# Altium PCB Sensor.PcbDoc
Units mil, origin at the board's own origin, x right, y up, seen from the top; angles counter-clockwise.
Board outline 4560.03 x 3240.01 mil, 2 copper layers (Top Layer, Bottom Layer); 112 components, 74 nets, 343 pads, 74 vias.
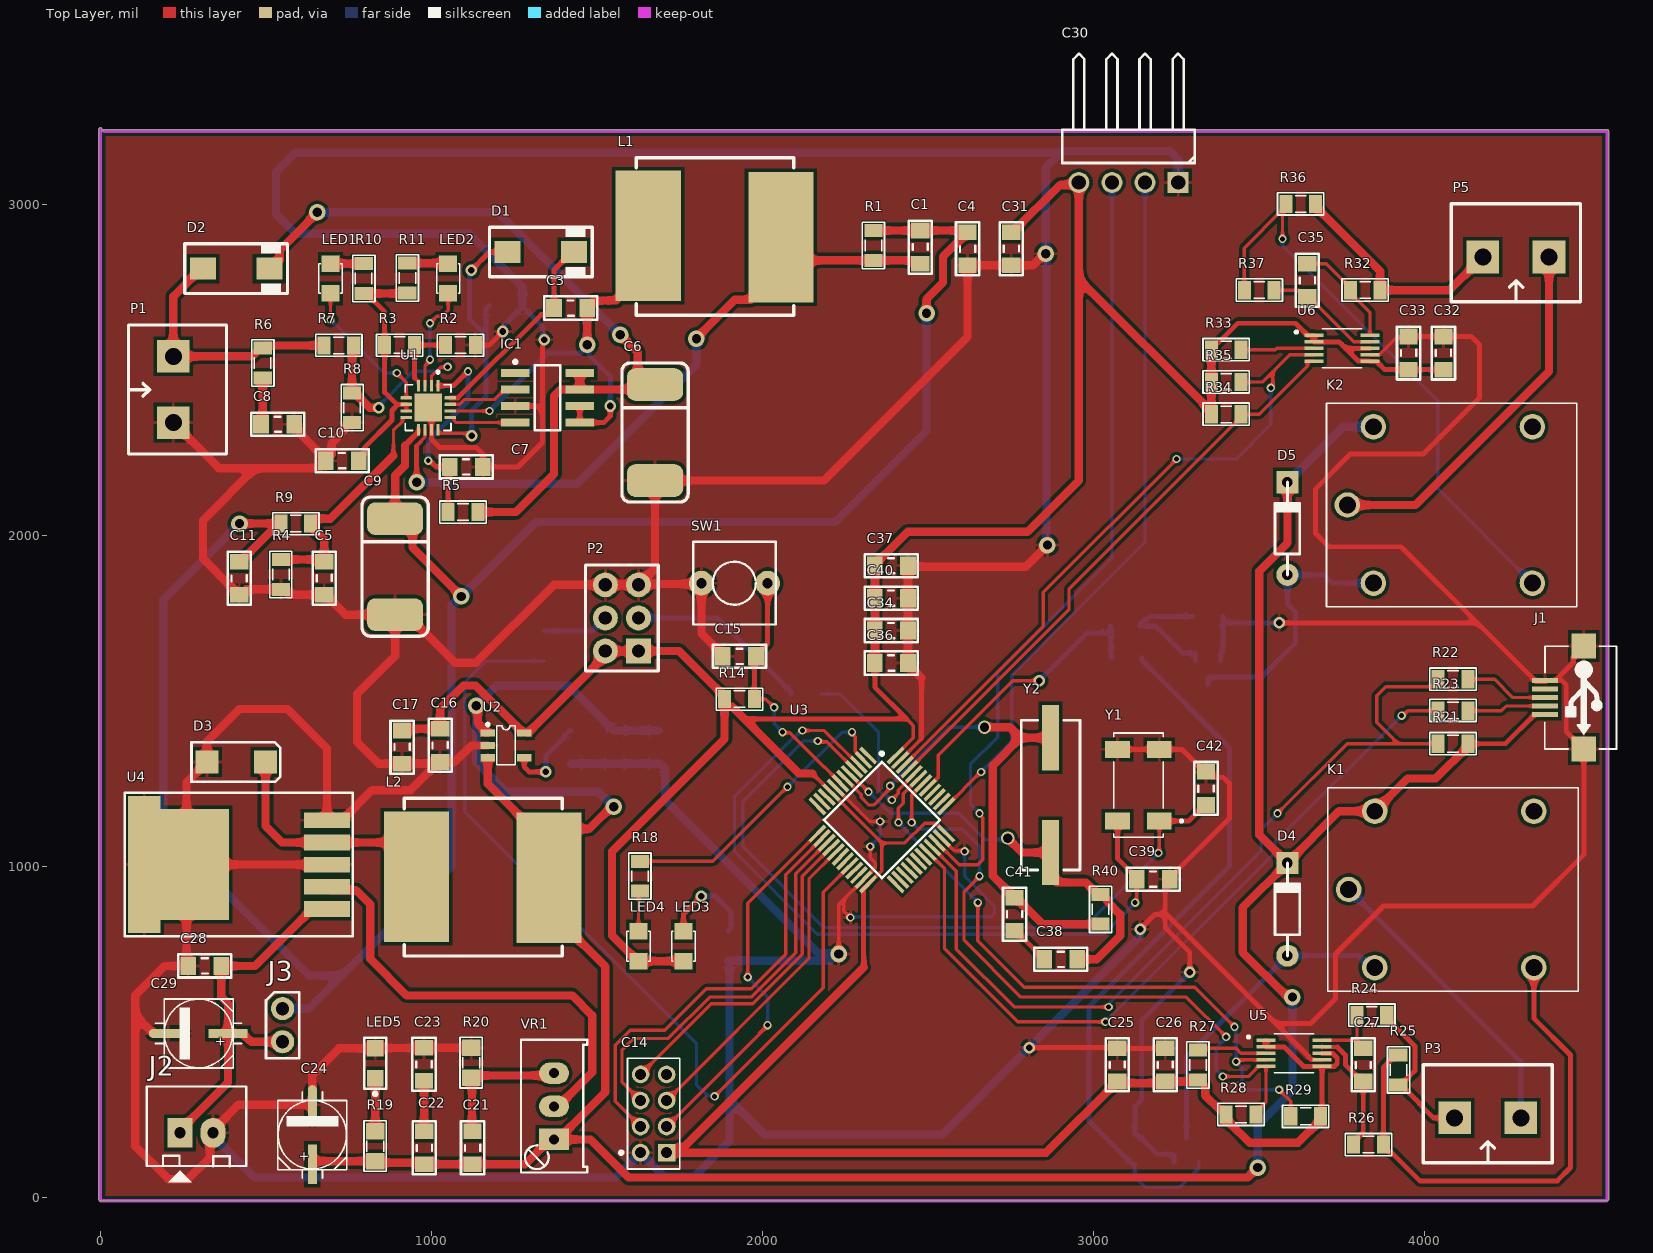
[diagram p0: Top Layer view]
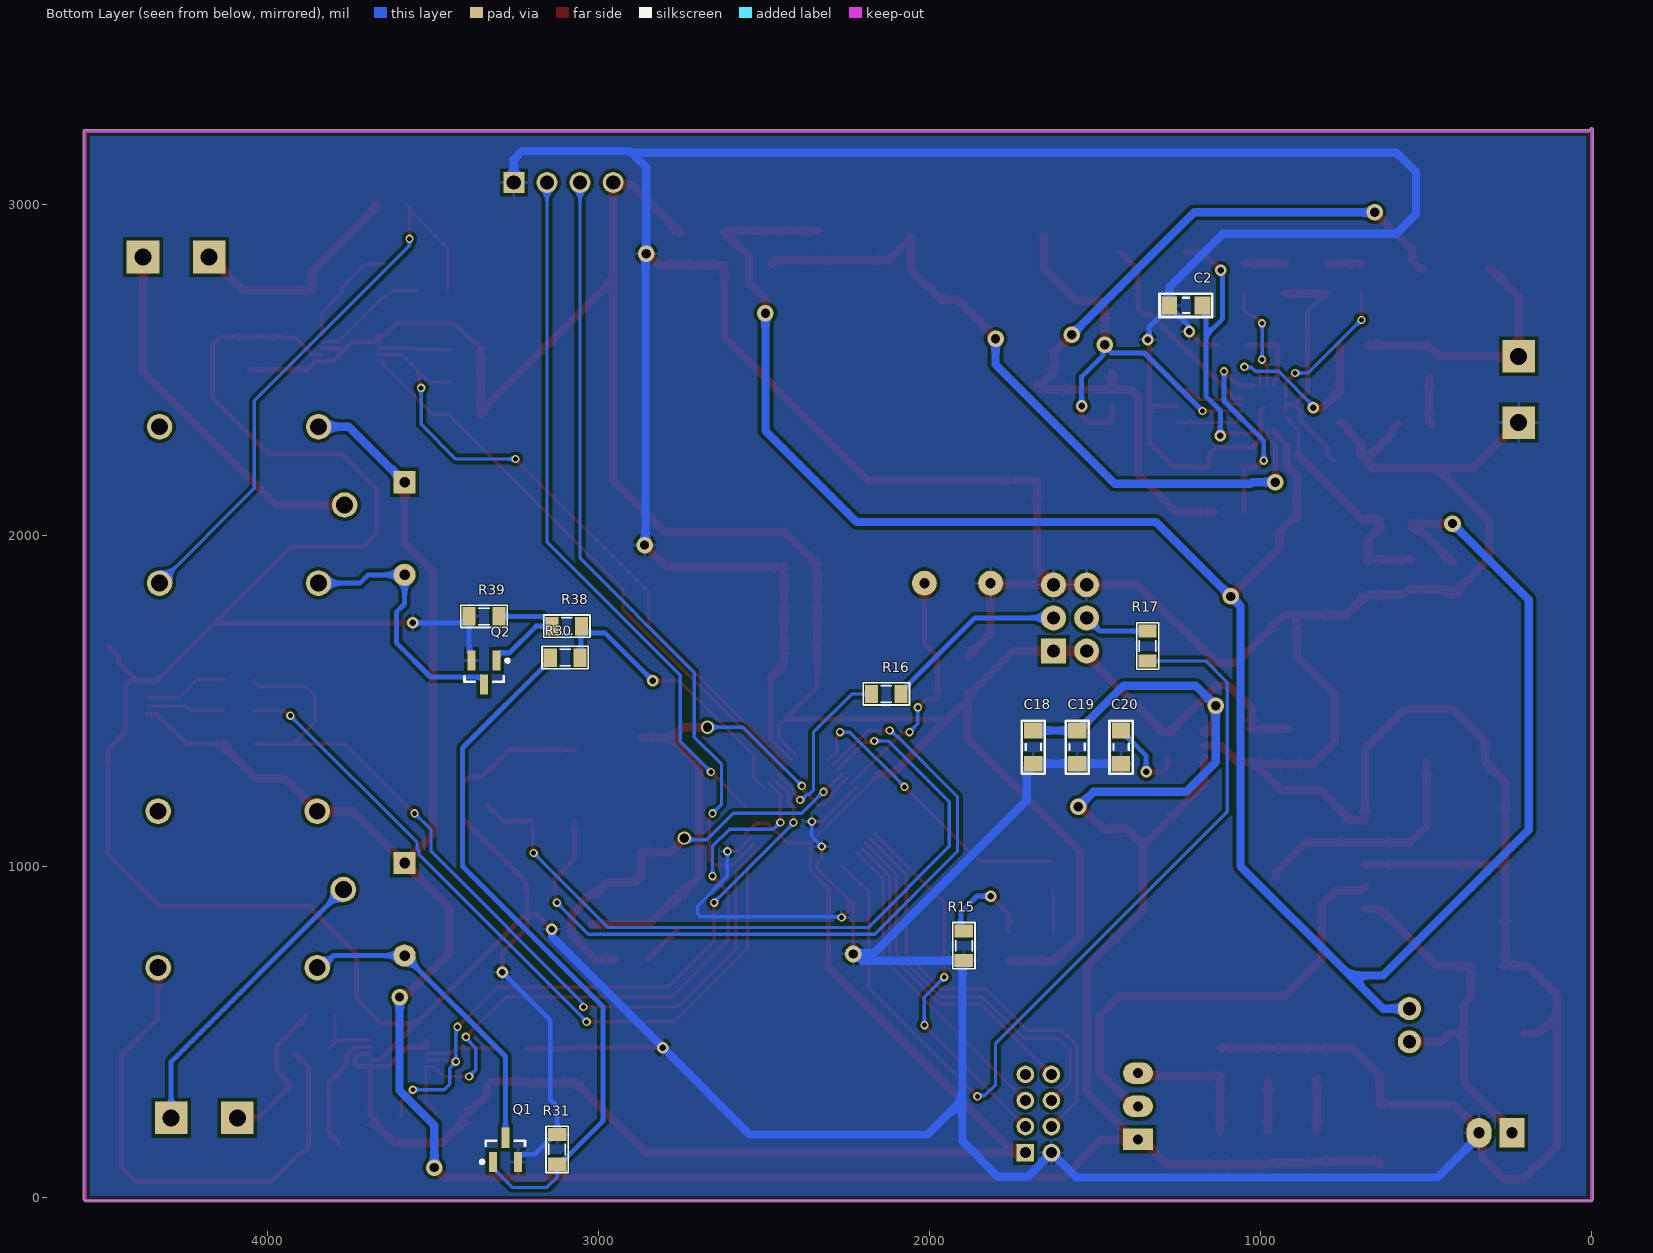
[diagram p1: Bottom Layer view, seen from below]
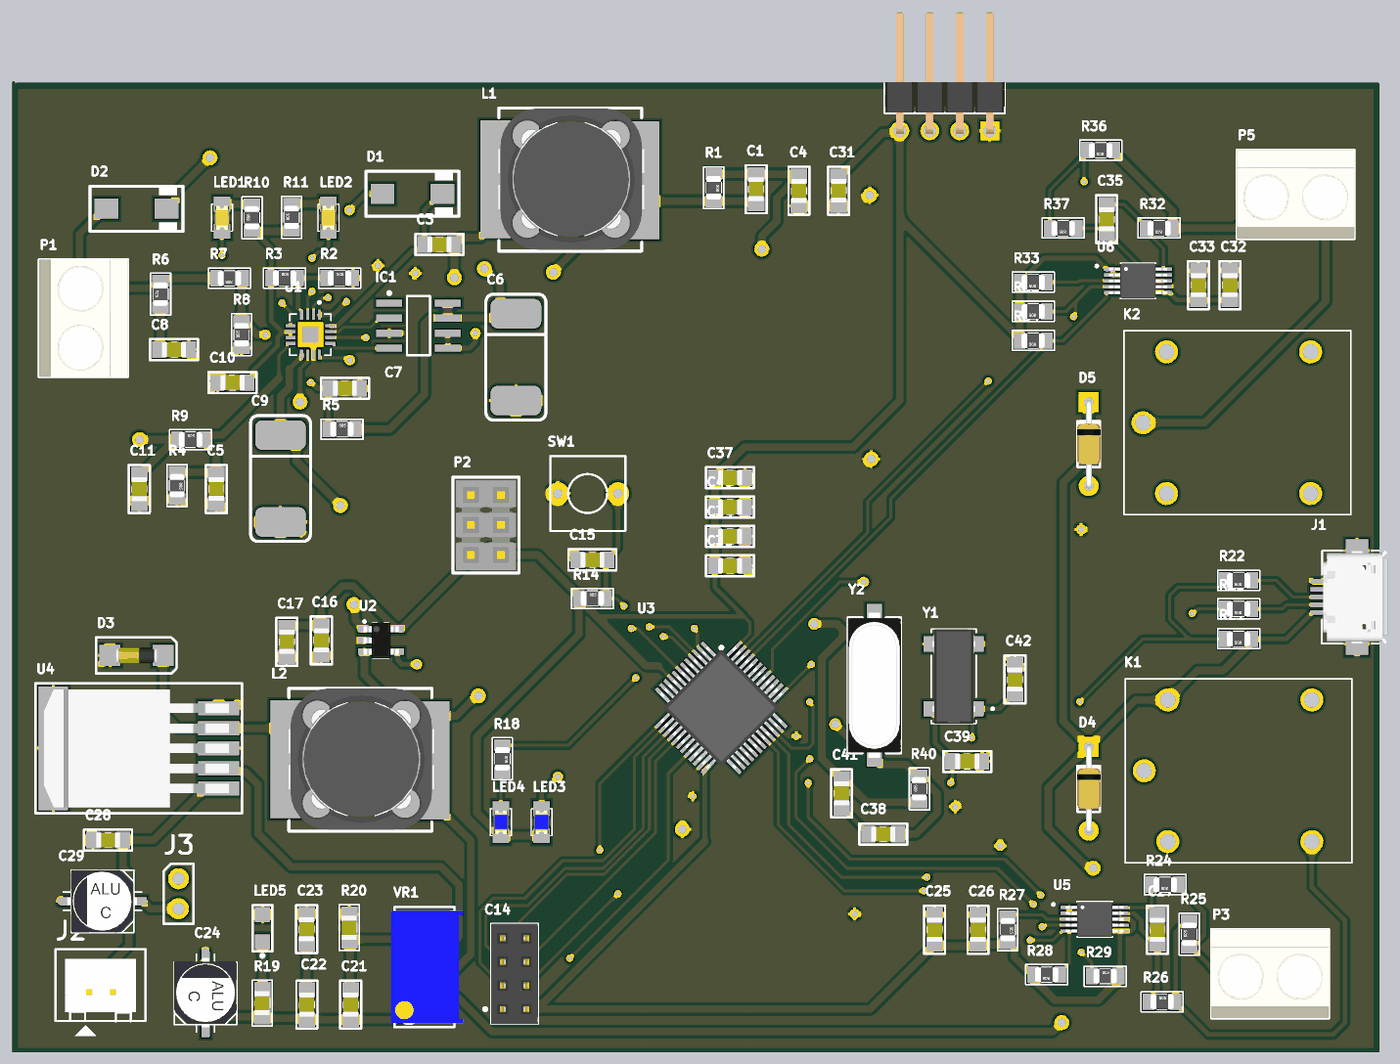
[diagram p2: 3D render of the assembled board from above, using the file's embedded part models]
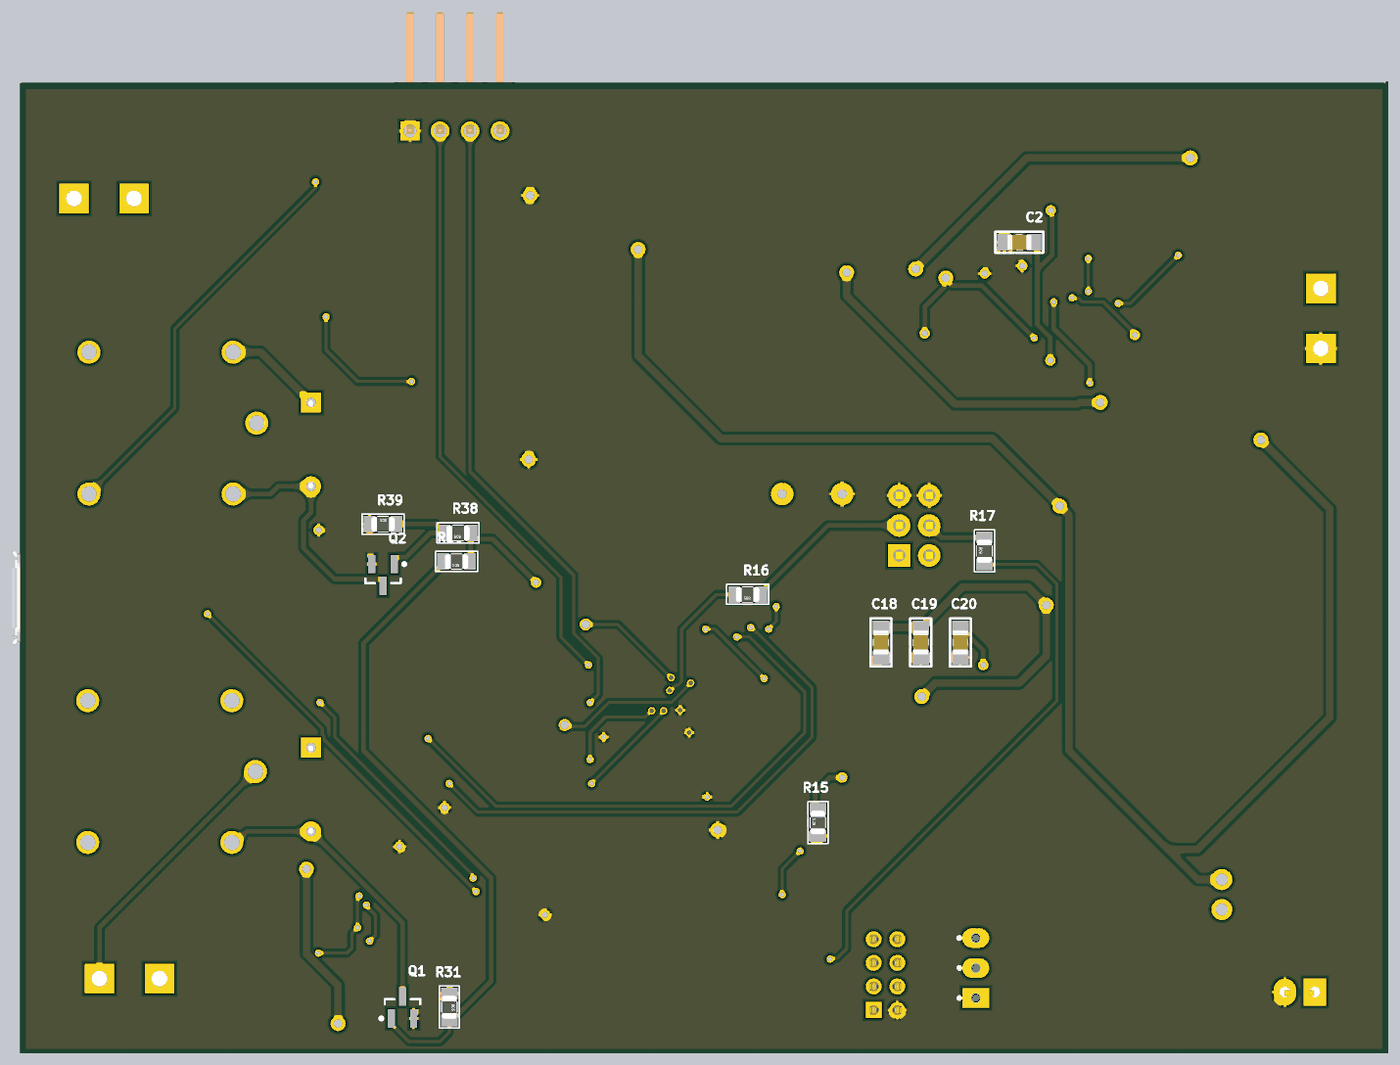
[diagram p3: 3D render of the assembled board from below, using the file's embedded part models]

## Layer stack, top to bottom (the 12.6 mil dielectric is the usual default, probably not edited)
Top Solder: solder mask 0.4, Solder Resist, Dk 3.5
Top Layer: signal copper 1.4
Dielectric 1: dielectric 12.6, FR-4, Dk 4.8
Bottom Layer: signal copper 1.4
Bottom Solder: solder mask 0.4, Solder Resist, Dk 3.5

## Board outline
0,-10.02 cw(c0,-5) -5.02,-5 -5.02,3225 cw(c0,3225) 5.02,3225 5.02,3220.55 cw(c10,3220) 10,3225.02 4550,3225.02 cw(c4550,3220) 4555.02,3220 4555.02,-5 cw(c4550,-5) 4550,-10.02

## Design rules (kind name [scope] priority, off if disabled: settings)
Clearance [All] p1: gap=10 ignorepadtopadclearanceinfootprint=FALSE
PolygonConnect [All] p1: connectstyle=Relief reliefconductorwidth=10 reliefentries=4 polygonreliefangle="90 Angle" airgapwidth=10
RoutingVias [All] p1: holewidth=20 width=35 viastyle="Through Hole" minholewidth=15 minwidth=25 maxholewidth=28 maxwidth=50
SilkToSilkClearance [IsText] p1: silktosilkclearance=10
SolderMaskExpansion [All] p1: expansion=4 istentingtop=FALSE
Width [All] p1: maxlimit=25 minlimit=10 preferedwidth=15
29 further rules are at their usual default settings.

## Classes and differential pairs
component class U_Sensor: C14 C15 C16 C17 C18 C19 C20 C21 C22 C23 C24 C25 C26 C27 C28 C29 C30 C31 C32 C33 C34 C35 C36 C37 C38 C39 C40 C41 C42 D3 D4 D5 J1 K1 K2 L2 LED3 LED4 LED5 P2 P3 P5 Q1 Q2 R14 R15 R16 R17 R18 R19 R20 R21 R22 R23 R24 R25 R26 R27 R28 R29 R30 R31 R32 R33 R34 R35 R36 R37 R38 R39 R40 SW1 U2 U3 U4 U5 U6 VR1 Y1 Y2
component class U_MPPT: C1 C2 C3 C4 C5 C6 C7 C8 C9 C10 C11 D1 D2 IC1 J2 J3 L1 LED1 LED2 P1 R1 R2 R3 R4 R5 R6 R7 R8 R9 R10 R11 U1

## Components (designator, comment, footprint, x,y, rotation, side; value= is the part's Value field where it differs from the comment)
C1 "10uF" CAP_0805 2475,2870 r90 top value=33p
C2 "2.2uF" CAP_0805 1225,2695 r180 bottom value=33p
C3 "2.2uF" CAP_0805 1420,2687 r0 top value=33p
C4 "10uF" CAP_0805 2620,2865 r270 top value=33p
C5 "100uF" CAP_0805 675,1870 r90 top value=33p
C6 "220uF/25V" CAP_7343 1675,2305 r270 top
C7 "100nF" CAP_0805 1105,2205 r180 top value=33p
C8 "2.2uF" CAP_0805 535,2336 r0 top value=33p
C9 "100uF/16V" CAP_7343 890,1900 r270 top
C10 "0.1nF" CAP_0805 730,2224 r180 top value=33p
C11 "22uF" CAP_0805 420,1870 r270 top value=33p
C14 "JP4x2-2.0" J4-C2T 1670.63,253.11 r90 top
C15 "105" CAP_0805 1930,1635 r0 top value=33p
C16 "106" CAP_0805 1025,1365 r90 top value=33p
C17 "104" CAP_0805 910,1360 r90 top value=33p
C18 "105" CAP_0805 1687,1360 r90 bottom value=33p
C19 "104" CAP_0805 1554.5,1360 r90 bottom value=33p
C20 "223" CAP_0805 1422,1360 r90 bottom value=33p
C21 "22pF" CAP_0805 1125,150 r270 top
C22 "100nF/50V" CAP_0805 979.22,150 r270 top
C23 "100nF/50V" CAP_0805 978.22,402 r270 top
C24 "Cap Pol SMD" CAP-ALU-SMD-C 640,190 r90 top value=100uF/63V
C25 "0.1uF" CAP_0805 3070,400 r90 top value=33p
C26 "0.1uF" CAP_0805 3215,400 r90 top value=33p
C27 "0.1uF" CAP_0805 3815,400 r270 top value=33p
C28 "1uF/50V" CAP_0805 315,700 r0 top
C29 "Cap Pol SMD" CAP-ALU-SMD-C 295,495 r180 top value=100uF/50V
C30 "JP4" JP4-D1C 2905,3165 r180 top
C31 "104" CAP_0805 2750,2865 r90 top value=33p
C32 "0.1uF" CAP_0805 4055,2550 r90 top value=33p
C33 "0.1uF" CAP_0805 3950,2550 r90 top value=33p
C34 "104" CAP_0805 2388.94,1710.81 r180 top value=33p
C35 "0.1uF" CAP_0805 3646,2770 r270 top value=33p
C36 "104" CAP_0805 2388.94,1612.94 r180 top value=33p
C37 "104" CAP_0805 2388.94,1906.56 r180 top value=33p
C38 "20p" CAP_0805 2900,720 r0 top value=33p
C39 "20p" CAP_0805 3180,960 r180 top value=33p
C40 "104" CAP_0805 2388.94,1808.68 r180 top value=33p
C41 "20p" CAP_0805 2760,855 r90 top value=33p
C42 "20p" CAP_0805 3340,1235 r270 top value=33p
D1 "1N5822" SMA 1330,2855 r0 top value="Diode c?m 1N5408"
D2 "1N5822" SMA 409.84,2805 r0 top value="Diode c?m 1N5408"
D3 "Diode Zener" DIODE_ZENER_SMD 410,1315 r0 top
D4 "Diode 1N4148" DO-35 3585,870 r90 top
D5 "Diode 1N4148" DO-35 3585,2020 r90 top
IC1 "AO4914" Soic-8 1350,2405 r0 top
J1 "USB-5" USB-M1 4363.16,1509.49 r270 top
J2 "JP2" CON2 240,195 r0 top
J3 "JP2" JP2-CLOSED 550,570 r0 top
K1 "SRD-03VDC-SL-C" RELAY_SRD-03VDC-SL-C 4085,930 r0 top
K2 "SRD-03VDC-SL-C" RELAY_SRD-03VDC-SL-C 4080.91,2091.22 r0 top
L1 "15uH" Inductor_SMD 2094.37,2663.78 r90 top value="150 mH"
L2 "33uH" Inductor_SMD 1394.37,728.78 r90 top value="150 mH"
LED1 "LED" LED-0805-Yellow 695,2820 r270 top value="LED 3 ly Single Colour"
LED2 "LED" LED-0805-Yellow 1050,2820 r270 top value="LED 3 ly Single Colour"
LED3 "LED" LED-0805-Blue 1760.75,713.5 r90 top value="LED 3 ly Single Colour"
LED4 "LED" LED-0805-Blue 1625,713.5 r90 top value="LED 3 ly Single Colour"
LED5 "LED" LED0805 830,405 r90 top value="LED 3 ly Single Colour"
P1 "Pin" KF2-5.08 220,2440 r90 top
P2 "Header 3x2" "Header 3x2" 1625,1650 r90 top
P3 "INA_ref" KF2-5.08 4190,240 r180 top
P5 "INA_sensor" KF2-5.08 4275,2840 r180 top
Q1 "C1815" "SOT23 [C1815]" 3280.16,143.58 r90 bottom
Q2 "C1815" "SOT23 [C1815]" 3345,1585 r270 bottom
R1 "0R04" RES-SMD-0805 2335,2875 r270 top
R2 "10k" RES-SMD-0805 1087.11,2574.02 r0 top
R3 "6k8" RES-SMD-0805 903.56,2574.02 r0 top
R4 "10k" RES-SMD-0805 545.06,1881.44 r270 top
R5 "10R" RES-SMD-0805 1095,2070 r0 top
R6 "2k" RES-SMD-0805 490,2520 r90 top
R7 "??" RES-SMD-0805 720,2573.02 r180 top
R8 "??" RES-SMD-0805 760,2385 r90 top
R9 "30k" RES-SMD-0805 590,2035 r0 top
R10 "1.5k" RES-SMD-0805 795,2775 r90 top
R11 "1.5k" RES-SMD-0805 926.83,2776.5 r90 top
R14 "10k" RES-SMD-0805 1930,1505 r0 top
R15 "510R" RES-SMD-0805 1896,760 r90 bottom
R16 "100k" RES-SMD-0805 2130,1520 r0 bottom
R17 "100k" RES-SMD-0805 1341,1665 r90 bottom
R18 "510R" RES-SMD-0805 1630,970 r270 top
R19 "1% 1K" SM-0805 830,154.44 r270 top value=1K
R20 "1K" SM-0805 1120,406.44 r270 top
R21 "4.7k" RES-SMD-0805 4085,1370 r180 top
R22 "20R" RES-SMD-0805 4085,1565 r180 top
R23 "20R" RES-SMD-0805 4085,1470 r180 top
R24 "10R" RES-SMD-0805 3840,550 r180 top
R25 "10mR" RES-SMD-0805 3920,385 r90 top
R26 "10R" RES-SMD-0805 3830,160 r0 top
R27 "4.7K" RES-SMD-0805 3315,400 r270 top
R28 "4.7K" RES-SMD-0805 3445,250 r180 top
R29 "4.7K" RES-SMD-0805 3640,245 r0 top
R30 "330R" RES-SMD-0805 3100,1630 r0 bottom
R31 "100k" RES-SMD-0805 3124,145 r270 bottom
R32 "10R" RES-SMD-0805 3820,2740 r180 top
R33 "4.7K" RES-SMD-0805 3400,2560 r180 top
R34 "4.7K" RES-SMD-0805 3400,2365 r180 top
R35 "4.7K" RES-SMD-0805 3400,2462.5 r180 top
R36 "10mR" RES-SMD-0805 3625,3000 r180 top
R37 "10R" RES-SMD-0805 3500,2740 r180 top
R38 "330R" RES-SMD-0805 3095,1725 r0 bottom
R39 "100k" RES-SMD-0805 3345,1755 r180 bottom
R40 "1M" RES-SMD-0805 3020,870 r90 top
SW1 "SW" SW2 1815,1855 r0 top value="SW chip 2 pin"
U1 "BQ24650RVAT" QFN50P350X350X100-17N 990,2385 r270 top
U2 "RT9193-33GB" SOT23-5AL 1225,1365 r0 top
U3 "STM32F103C8T6" LQFP-48_19.6_393_58X11_SMD 2360,1140 r315 top
U4 "LM2596" TO263-5 702.91,1005 r90 top
U5 "INA226AIDGSR" SOP50P490X110-10N 3605,435 r0 top
U6 "INA226AIDGSR" SOP50P490X110-10N 3749.65,2564.37 r0 top
VR1 "10K" VR1 1370,175 r90 top value="VR 10K"
Y1 "MC-306_32.768K-E3" XTAL_MC-306_32.768K-E3 3135,1245 r180 top
Y2 "8MHz" XTAL_SMD 2870,1215 r270 top

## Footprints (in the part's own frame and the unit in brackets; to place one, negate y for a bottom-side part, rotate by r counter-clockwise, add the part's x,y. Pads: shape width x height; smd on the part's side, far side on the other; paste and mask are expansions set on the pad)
CAP-ALU-SMD-C [mm]
  rect 3x0.7 smd: 1(-2.286,0)
  oval 3x0.7 smd: 2(2.286,0)
  silkscreen extent -3.35,-2.65 3.28,2.65, body extent -2.95,-2.65 2.95,2.65, height 5.41
CAP_0805 [mm]
  rect 1.2x1.4 smd: 1(-1.27,-0.025) 2(1.27,-0.025)
  silkscreen extent -2.03,-0.91 2.03,0.86, body extent -1.01,-0.66 1.01,0.61, height 0.61
CAP_7343 [mm] "Capacitor Tantalum 7343"
  rrect50% 2.5x4.3 smd: 1(-3.81,0) 2(3.556,0)
  silkscreen extent -5.46,-2.54 5.21,2.54, body extent -3.81,-2.29 3.56,2.29, height 3
CON2 [mil] "CON2"
  rect 75x90 hole 34: 1(0,0)
  oval 75x90 hole 34: 2(100,0)
  silkscreen extent -100,-150 200,140, body extent -68,-70 168,107, height 236
DIODE_ZENER_SMD [mil]
  rect 70x70 smd: 1(-88.58,0) 2(88.58,0)
  silkscreen extent -135,-60 134,60, body extent -69,-29 69,29, height 57
DO-35 [mil] "Diode, Axial; Body 3.8 x 1.9 mm (LxDia. max), Lead Dia. 0.53 mm (max); Solder Pad 35mil"
  round 67 hole 32: 1(-139.76,0)
  rect 67x67 hole 32: 2(139.76,0)
  silkscreen extent -140,-37 140,37, body extent -148,-40 148,39, height 89
"Header 3x2" [mil] "Connector; Header; 6 Position; 2 Row; Solder Pad 35mil"
  rect 75x75 hole 40: 1(0,0)
  round 75 hole 40: 2(0,100) 3(100,0) 4(100,100) 5(200,0) 6(200,100)
  silkscreen extent -60,-60 260,160, body extent -50,-50 250,150, height 83
Inductor_SMD [mm]
  rect 10x5 smd: 1(6.096,11.176) 2(6,1)
  silkscreen extent 0,0 12.1,12.1, body extent 0.1,-0.2 12.1,12.14, height 7.15
J4-C2T [mm] "8 pins, dual row, straight, gold plating"
  rect 1.35x1.35 hole 0.85: 1(-3,-1)
  round 1.35 hole 0.85: 2(-1,-1) 3(1,-1) 4(3,-1) 5(3,1) 6(1,1) 7(-1,1) 8(-3,1)
  silkscreen extent -4.25,-2 4.25,2.61, body extent -4.25,-2 4.25,2, height 4.31
JP2-CLOSED [mil]
  round 70 hole 40: 1(0,0) 2(0,-100)
  silkscreen extent -50,-150 50,50, body extent -50,-152 50,50, height 300
JP4-D1C [mm] "4 pins, 1 row, right angled, gold plating"
  rect 1.6x1.6 hole 1.1: 1(-8.89,2.54)
  round 1.6 hole 1.1: 2(-6.35,2.54) 3(-3.81,2.54) 4(-1.27,2.54)
  silkscreen extent -10.16,-7.34 0,1.04, body extent -10.16,-7.57 0,2.79, height 2.54
KF2-5.08 [mm]
  rect 2.5x2.5 hole 1.3: 1(-2.54,0) 2(2.54,0)
  silkscreen extent -4.95,-4.08 4.95,3.43, body extent -5,-4.07 5,3.43, height 10
LED0805 [mil] "Chip Resistor; Body 2.0 x 1.3 mm (LxW typ)"
  rect 50x50 smd: 1(-45,0) 2(45,0)
  silkscreen extent -97,-33 77,33, body extent -60,-25 60,25, height 47
LED-0805-Blue [mil]
  rect 50x55 smd: 1(0,0) 2(90,0)
  silkscreen extent 0,-35 90,35, body extent 5,-25 85,25, height 43
LED-0805-Yellow [mil]
  rect 50x55 smd: 1(0,0) 2(90,0)
  silkscreen extent 0,-35 90,35, body extent 5,-25 85,25, height 43
LQFP-48_19.6_393_58X11_SMD [mm] "48LQFP"
  rect 1.7x0.3 smd mask+0.076: 1(-4.238,2.75) 2(-4.238,2.25) 3(-4.238,1.75) 4(-4.238,1.25) 5(-4.238,0.75) 6(-4.238,0.25) 7(-4.238,-0.25) 8(-4.238,-0.75) 9(-4.238,-1.25) 10(-4.238,-1.75) 11(-4.238,-2.25) 12(-4.238,-2.75) 25(4.238,-2.75) 26(4.238,-2.25) 27(4.238,-1.75) 28(4.238,-1.25) 29(4.238,-0.75) 30(4.238,-0.25) 31(4.238,0.25) 32(4.238,0.75) 33(4.238,1.25) 34(4.238,1.75) 35(4.238,2.25) 36(4.238,2.75)
  rect 0.3x1.7 smd mask+0.076: 13(-2.75,-4.238) 14(-2.25,-4.238) 15(-1.75,-4.238) 16(-1.25,-4.238) 17(-0.75,-4.238) 18(-0.25,-4.238) 19(0.25,-4.238) 20(0.75,-4.238) 21(1.25,-4.238) 22(1.75,-4.238) 23(2.25,-4.238) 24(2.75,-4.238) 37(2.75,4.238) 38(2.25,4.238) 39(1.75,4.238) 40(1.25,4.238) 41(0.75,4.238) 42(0.25,4.238) 43(-0.25,4.238) 44(-0.75,4.238) 45(-1.25,4.238) 46(-1.75,4.238) 47(-2.25,4.238) 48(-2.75,4.238)
  silkscreen extent -3.72,-3.15 3.15,3.72, body extent -4.5,-4.5 4.5,4.5, height 1.7
QFN50P350X350X100-17N [mm]
  rrect25% 0.86x0.26 smd: 1(-1.685,0.75) 2(-1.685,0.25) 3(-1.685,-0.25) 4(-1.685,-0.75) 9(1.685,-0.75) 10(1.685,-0.25) 11(1.685,0.25) 12(1.685,0.75)
  rrect25% 0.26x0.86 smd: 5(-0.75,-1.685) 6(-0.25,-1.685) 7(0.25,-1.685) 8(0.75,-1.685) 13(0.75,1.685) 14(0.25,1.685) 15(-0.25,1.685) 16(-0.75,1.685)
  rect 2.14x2.14 smd paste-2: 17(0,0)
  silkscreen extent -2.82,-1.75 1.75,1.75
RELAY_SRD-03VDC-SL-C [mm]
  round 1.95 hole 1.3: COIL1(-6,6) COIL2(-6,-6) COM(-8,0) NC(6.2,6) NO(6.2,-6)
  silkscreen extent -9.6,-7.8 9.6,7.8
RES-SMD-0805 [mil]
  rect 39.37x55 smd: 1(-45,0) 2(45,0)
  silkscreen extent -70,-34 70,33, body extent -39,-25 39,25, height 31
SM-0805 [mil] "Compoment SMD 80x50mil"
  rect 50x55 smd: 1(-45,0) 2(45,0)
  silkscreen extent -77,-34 76,33, body extent -40,-27 40,23, height 24
SMA [mm]
  rect 2x1.7 smd: 1(-2.544,0) 2(2.544,0)
  silkscreen extent -3.94,-1.9 3.94,1.91, body extent -2.87,-1.4 2.87,1.4, height 2.29
Soic-8 [mm]
  rect 2.2x0.6 smd: 1(-2.467,2.159) 2(-2.467,0.889) 3(-2.467,-0.381) 4(-2.467,-1.651) 5(2.483,-1.651) 6(2.483,-0.381) 7(2.483,0.889) 8(2.483,2.159)
  silkscreen extent -2.59,-2.25 0.98,3.13, body extent -3.19,-2.25 3.21,2.75, height 1.75
SOP50P490X110-10N [mm]
  rrect25% 1.47x0.28 smd: 1(-2.15,1) 2(-2.15,0.5) 3(-2.15,0) 4(-2.15,-0.5) 5(-2.15,-1) 6(2.15,-1) 7(2.15,-0.5) 8(2.15,0) 9(2.15,0.5) 10(2.15,1)
  silkscreen extent -3.6,-1.5 1.5,1.5, body extent -2.45,-1.5 2.45,1.5, height 1.1
"SOT23 [C1815]" [mm] "SOT23, 3-Leads, Body 3.0x2.6mm (max), Pitch 0.95mm, IPC Medium Density"
  rect 1.55x0.6 smd: 1(-0.925,0.95) 2(-0.925,-0.95) 3(0.925,0)
  silkscreen extent -1.05,-1.5 0.7,1.93, body extent -1.53,-1.5 1.53,1.5, height 1.1
SOT23-5AL [mm] "SOT23, 5-Leads, Body 2.9x1.6mm, Pitch 0.95mm, Lead Span 2.8mm, IPC High Density"
  rect 1.1x0.55 smd: 1(-1.4,0.95) 2(-1.4,0) 3(-1.4,-0.95) 4(1.4,-0.95) 5(1.4,0.95)
  silkscreen extent -1.6,-1.5 0.7,1.8, body extent -1.48,-1.5 1.52,1.5, height 1.3
SW2 [mil] "SW button 2pin, 250x 250 mil"
  round 75 hole 31: 1(0,0) 2(200,0)
  silkscreen extent -25,-125 225,125
TO263-5 [mm] "LM2576-SMD"
  rect 1.2x3.5 smd: 1(-3.4,0.475) 2(-1.7,0.475) 3(0,0.475) 4(1.7,0.475) 5(3.4,0.475)
  rect 10.5x2.5 smd: 6(0,14.5)
  rect 8.5x6.5 smd: 6(0,11.25)
  silkscreen extent -5.5,-1.5 5.5,16, body extent -5,-0.38 5,15.29, height 4.79
USB-M1 [mm]
  rect 0.4x2 smd: 1(1.3,0) 2(0.65,0) 3(0,0) 4(-0.65,0) 5(-1.321,0)
  rect 1.9x1.9 smd: 5(-3.95,2.968) 5(3.95,2.968)
  silkscreen extent -3.94,-0.03 3.94,5.46, body extent -3.98,0.11 4,5.54, height 2.71
VR1 [mil] "Variable Resistor"
  rect 65x90 hole 30: 1(0,0)
  oval 65x90 hole 30: 2(100,0) 3(200,0)
  silkscreen extent -100,-100 301,100, body extent -88,-130 288,110, height 455
XTAL_MC-306_32.768K-E3 [mm]
  rect 1.9x1.3 smd: 1(-1.6,2.75) 2(-1.6,-2.75) 3(1.6,-2.75) 4(1.6,2.75)
  silkscreen extent -3.4,-4 1.9,4, body extent -1.85,-4 1.85,4, height 2.54
XTAL_SMD [mm]
  rect 5x1.3 smd: 1(-4.4,0.001) 2(4.4,0.001)
  silkscreen extent -5.75,-2.25 5.75,2.25, body extent -6.15,-2.25 6.15,2.25, height 5.18

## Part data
C1 C2 C3 C4 C5 C7 C8 C10 C11 C15 C16 C17 C18 C19 C20 C25 C26 C27 C31 C32 C33 C34 C35 C36 C37 C38 C39 C40 C41 C42: library part CapSMD, "Capacitor"
C6 C9: library part CAP_TAN_SMD, "Polazied Tantalum Capacitor"
C14: "WR-PHD 2.00 mm Dual Pin Header", Manufacturer="W¨¹rth Elektronik eiSos GmbH", partNo=62000821121
C21 C22 C23 C28: library part "Cap SMD 1206"
C24 C29: "Polarized Capacitor (Radial)"
C30: "WR-PHD 2.54 mm Angled Socket Header", Manufacturer="W¨¹rth Elektronik eiSos GmbH", partNo=613004143121
D1 D2: "Schottky Rectifiers"
D3: "Zener Diode"
D4 D5: "High Conductance Fast Diode"
J1: Manufacturer=FCI, Manufacturer Part Number=10118193-0001LF, Supplier Part Number 1=609-4616-1-ND
J2 J3: "WR-PHD 2.54 mm Angled Socket Header", Manufacturer="W¨¹rth Elektronik eiSos GmbH", partNo=613002143121
K1 K2: "Relays General Purpose Non Latching 3VDC SPDT 10A (250VAC) Max 5PIN", Package=Package
L1 L2: library part L1, "Inductor"
LED1 LED2 LED3 LED4 LED5: "LED Single colour Green and Red"
P1 P3 P5: library part "Header 2", "Header, 2-Pin"
P2: "Header, 6-Pin, 2-Row"
Q1 Q2: "Q2SC1815", PSpiceTemplate="Q^@REFDES %c %b %e @MODEL"
R1 R2 R3 R4 R5 R6 R7 R8 R9 R10 R11 R14 R15 R16 R17 R18 R21 R22 R23 R24 R25 R26 R27 R28 R29 R30 R31 R32 R33 R34 R35 R36 R37 R38 R39 R40: library part "Resistor - SMD", "Resistor", Manufacturer="Generic Components"
R19 R20: library part RM, "Resistor SMD"
SW1: library part SW2, "Switch button 2 pin"
U1: "High efficiency synchronous switch-mode charger controller solar battery charger 16-VQFN -40 to 85", Package="VQFN-16 Texas Instruments"
U2: library part RT9193, "1A Regulator"
U3: library part IC_STM32F103C8T6, "ARM® Cortex®-M3 STM32F1 Microcontroller IC 32-Bit 72MHz 64KB (64K x 8) FLASH 48-LQFP (7x7)", Alternate Part Number-1=NA, Case/Package=LQFP48, Manufacturer=STMicroelectronics
U4: "1A Regulator"
U5 U6: "36V, 16-bit, ultra-precise i2c output current/voltage/power monitor w/alert", Package="VSSOP-10 Texas Instruments"
VR1: library part VR1, "Var Resistor"
Y1: "CRYSTAL 32.7680KHZ 6PF SMD", Package="NON STANDARD-4 EPSON"
Y2: library part XTAL, "Crystal Oscillator"

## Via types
v1: diameter 25, hole 15, Top Layer to Bottom Layer, 44 vias
v2: diameter 50, hole 28, Top Layer to Bottom Layer, 15 vias
v3: diameter 35, hole 20, Top Layer to Bottom Layer, 13 vias
v4: diameter 40, hole 28, Top Layer to Bottom Layer, 2 vias

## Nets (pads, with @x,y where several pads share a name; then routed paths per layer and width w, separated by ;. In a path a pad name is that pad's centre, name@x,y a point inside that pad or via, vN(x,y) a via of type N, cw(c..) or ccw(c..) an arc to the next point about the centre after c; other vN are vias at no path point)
+5: C18.2 C19.2 C21.2 C22.2 C24.1 D4.2 D5.2 J1.1 K1.COIL1 K2.COIL1 L2.2 R19.2 R21.1 U2.1 U2.3 VR1.1 | length 9542.5
  Top Layer w15: R21.1 4243.35,1370 4331.66,1458.31 J1.1
  Top Layer w25: C24.1 640,108.16 641.28,109.44 R19.2 834.72,104.72 973.5,104.72 C22.2 C21.2 1282.5,100 1357.5,175 VR1.1 VR1.1@1382.5,175 ; v2(1135,1484.43) 1139.78,1479.64 1139.78,1432.5 1160.73,1411.56 1160.73,1404.07 1162.4,1402.4 U2.1 ; U2.3 1169.88,1248.54 L2.2@1355,1063.43 ; v2(1550,1180) 1543.24,1180 1476.28,1113.05 1404.62,1113.05 L2.2@1355,1063.43 ; v2(3495,90) 3465,60 1595,60 1480,175 VR1.1@1382.5,175 ; D5.2 3585,1976.88 3500,1891.88 3500,1094.76 D4.2 ; v2(3600,605) 3595.22,609.78 3580.22,609.78 3450,740 3450,874.76 D4.2 ; R21.1 4130,1362.19 4032.82,1265 3947.56,1265 K1.COIL1 3741.46,1166.22 D4.2 ; L2.2@1355,1063.43 L2.2 1355,866.57 1525,696.57 1525,317.5 VR1.1@1382.5,175
  Bottom Layer w25: v2(1550,1180) 1505,1225 1225,1225 1135,1315 1135,1485 1195,1545 1414.56,1545 1549.56,1410 C19.2 C18.2 ; v2(3495,90) 3495,217.57 3600,322.57 v2(3600,605) ; D5.2 3752.68,2327.44 K2.COIL1
BOOT0: R16.2 U3.44 | length 556.7
  Top Layer w10: v1(2390,1200) 2410,1220 2410,1230 2434.26,1254.26 2434.26,1254.74 2457.1,1277.58 U3.44
  Bottom Layer w10: R16.2 2235,1520 2350,1405 2350,1230 2362.99,1217.01 2368.93,1217.01 2385.94,1200 v1(2390,1200)
BOOT1: R17.1 U3.20 | length 2707.5
  Top Layer w10: v1(1855,305) 2183.36,633.36 2183.36,921.6 U3.20
  Bottom Layer w10: R17.1 1165,1620 1100,1555 1100,1165 1800,465 1800,340 1832.13,307.87 1852.13,307.87 v1(1855,305)
BTST: C3.1 D1.2 U1.16 | length 625.8
  Top Layer w15: U1.16 1079.53,2414.53 1330.94,2665.94 1353.88,2665.94 1370,2682.06 1370,2800.75 1424.25,2855 D1.2
GND: C2.1 C4.2 C5.1 C6.2 C7.1 C8.2 C9.2 C10.2 C11.2 C14.8 C15.1 C16.1 C17.1 C18.1 C19.1 C20.1 C23.1 C24.2 C25.2 C26.2 C28.1 C29.2 C30.1 C31.1 C32.2 C33.2 C34.1 C36.1 C37.1 C39.1 C40.1 C42.1 D3.1 IC1.3 J1.5 J2.2 LED5.2 P1.1 P2.5 P2.6 Q1.2 Q2.2 R2.2 R4.2 R8.1 R15.1 R20.1 R31.1 R39.1 SW1.1 U1.11 U1.17 U2.2 U3.8 U3.23 U3.35 U3.47 U4.3 U4.5 U4.6 U5.7 U6.7 Y1.2 Y1.3 | length 32330.4
  Top Layer w10: U3.8 2323.24,1135 v1(2355,1135) ; v2(2230,735) 2230,884.73 2245.14,899.86 ; v1(2265,845) 2245.14,864.86 2245.14,899.86 ; v1(2325,1060) 2325,1025 2340,1010 2340,994.73 U3.23 2245.14,899.86 ; U3.47 2480,1385.27 ; U3.35 2577.5,1047.78 2607.22,1047.78 v1(2610,1045) ; 3659.17,415.83 3689.13,415.83 U5.7 ; U6.7 3834.8,2545.2 3862.9,2545.2 3914.3,2596.59 3947.59,2596.59 C33.2
  Top Layer w15: U1.17 999.84,2375.16 999.84,2290.16 1025,2265 1135,2265 1155,2245 C7.1 1261,2206 1335,2280 1335,2375 ; R2.2 1174.02,2574.02 v3(1215,2615) ; IC1.3 1320,2390 1335,2375 ; 1335,2571.21 1335,2375 ; 2480,1385.27 2480,1568.94 ; v3(2805,452.29) 3068.71,452.29 C25.2 C26.2 ; Y1.3 Y1.2 3266.8,1353.27 3335.06,1285 C42.1 3355.12,1268.88 3391.12,1268.88 3410,1250 3410,1144.94 3230,964.94 C39.1 3216,947 3216,855 ; v3(3140,810) 3185,855 3216,855 ; 3216,859 3550,525 ; v3(3290,680) 3290,740 3216,814 3216,855 ; v3(3560,1735) 4158.15,1735 ; 3659.17,415.83 3658.01,416.99 3656.34,416.99 3648.21,425.12 3648.21,426.79 3550,525 ; C33.2 C32.2 4140,2600 4165,2575 4165,2415 3995,2245 3775,2245 3670,2140 3670,2005 3710,1965 3928.15,1965 4158.15,1735 ; J1.5@4363.16,1561.49 J1.5@4394.65,1561.49 ; J1.5@4366.03,1558.61 4334.54,1558.61 4158.15,1735 ; J1.5@4480,1665 4447.6,1632.6 4447.6,1614.43 J1.5@4394.65,1561.49 ; 3550,525 3655,525 3730,600 3730,735 3875,880 4325,880 4480,1035 4480,1353.98 4427.13,1406.84 4427.13,1547.87 4413.51,1561.49 J1.5@4394.65,1561.49
  Top Layer w25: C29.2 159.72,495 105,549.72 ; P1.1 357.56,2202.44 467.44,2202.44 ; C8.2 603.62,2316.38 603.62,2305.31 680,2228.94 C10.2 ; U4.3 U4.6@260,1005 ; R8.1 752.19,2340 737.5,2325.31 737.5,2317.5 698.62,2278.62 698.62,2243.62 C10.2 ; R20.1 1119.72,451.72 977.5,451.72 C23.1 976.22,451 831,451 LED5.2 720,450 640,370 C24.2 417.5,280 340,202.5 J2.2 330.43,185.43 330.43,120.43 265,55 205,55 105,155 105,549.72 ; U2.2 1120,1365 1070,1315 C16.1 1022.06,1315 C16.1@1017.06,1310 ; C15.1 1880,1637.94 1815,1702.94 SW1.1 1812.5,1852.5 P2.5@1627.5,1852.5 ; 2480,1568.94 2438.94,1610 C36.1 C34.1 C40.1 C37.1 2441.5,1905 2795,1905 v2(2860,1970) ; v2(2855,2850) 2851.06,2850 2816.06,2815 C31.1 C4.2 2619,2599 2185,2165 C6.2 1675,1900 P2.5@1627.5,1852.5 ; 105,549.72 105,610 194,699 C28.1 260,704 U4.6@260,1005 ; U4.6@260,1005 260,1253.58 D3.1 321.42,1376.42 420,1475 565,1475 684.23,1355.77 U4.5 729.5,1138.86 820.65,1230 937.06,1230 C16.1@1017.06,1310 ; 467.44,2202.44 310,2045 310,1929 396.44,1842.56 396.44,1838.62 415.06,1820 C11.2 422.94,1820 439.38,1836.44 R4.2 552.88,1836.44 569.32,1820 C5.1 679.94,1820 739.94,1760 C9.2 ; 467.44,2202.44 661.38,2202.44 680,2221.06 C10.2 ; C9.2 925.43,1760 1070.43,1615 1135,1615 1370,1850 P2.6 P2.5 P2.5@1627.5,1852.5 ; C9.2 890,1635 775,1520 775,1375 840,1310 C17.1 C16.1@1017.06,1310
  Bottom Layer w10: v1(2265,845) 2267.5,847.5 2691.64,847.5 2700,855.86 2700,880 2610,970 v1(2610,1045) ; v1(2325,1060) 2355,1090 v1(2355,1135)
  Bottom Layer w15: v3(1215,2615) 1218.83,2618.83 1218.83,2633.89 C2.1@1275,2690.06 ; C2.1 C2.1@1275,2690.06 ; v3(1340,2590) 1336.17,2593.83 1336.17,2628.89 C2.1@1275,2690.06 ; v2(2855,2850) v2@2857.5,2847.5 ; 2890,3145 2905,3160 ; Q1.2 3242.76,125.87 3238.44,130.18 3191.64,130.18 3131.81,190 R31.1 3124,274 3145,295 3145,535 v3(3290,680) ; Q2.2 3382.4,1640.12 3390,1647.72 R39.1@3390,1749.69 ; R39.1 R39.1@3390,1749.69 ; v3(3560,1735) 3404.69,1735 R39.1@3390,1749.69
  Bottom Layer w25: J2.2 340,185 465,60 1556.26,60 C14.8 1704.12,62.14 1792.14,62.14 1900,170 1900,295 ; C2.1 1275,2750 1115,2910 590,2910 530,2970 530,3096.21 588.79,3155 2900,3155 ; C20.1 C19.1 C18.1 1689.94,1310 1706.06,1293.88 1706.06,1198.94 2167.5,737.5 2227.5,737.5 v2(2230,735) 2223.24,735 2203.23,715 R15.1 1900,711 1900,295 ; v2(2855,2850) 2855,3110 2890,3145 ; v2@2857.5,2847.5 2857.5,1972.5 v2(2860,1970) ; 2905,3160 3230,3160 3255,3135 C30.1 ; v3(3140,810) 3140,787.29 v3(2805,452.29) 2542.71,190 2005,190 1900,295
INA_SCL_r: R28.1 U3.42 U5.5 | length 2025.1
  Top Layer w10: v1(2450,1132.5) 2450,1216.08 U3.42 ; v1(2655,970) 2608.33,923.33 2608.33,776.67 2780,605 3280,605 v1(3400,485) ; v1(3390,365) 3466.3,365 3496.42,395.12 3519.84,395.12 U5.5 3520.35,288.17 3490,257.81 R28.1
  Bottom Layer w10: v1(2450,1132.5) 2470.83,1111.67 2603.33,1111.67 2655,1060 v1(2655,970) ; v1(3390,365) 3370,385 3370,450.94 3400,480.94 v1(3400,485)
INA_SCL_s: R34.1 U3.45 U6.5 | length 1781.7
  Top Layer w10: U3.45 2925,1774.6 2925,1837.19 3445,2357.19 R34.1 3500,2365 3645.35,2510.35 3645.35,2524.49 3645.86,2525 U6.5
INA_SDA_r: R29.1 U3.43 U5.4 | length 1985.9
  Top Layer w10: v1(2410,1132.5) 2410,1175 2425,1190 2425,1218.92 U3.43 ; v1(2650,890) 2650,775 2790,635 3305,635 v1(3425,515) ; v1(3430,410) 3435.31,415.32 U5.4 ; v1(3560,325) 3595,290 R29.1
  Bottom Layer w10: v1(2410,1132.5) 2410,1131.25 2650,891.25 v1(2650,890) ; v1(3425,515) 3430,510 v1(3430,410) 3430,408.98 3448.94,390.04 3448.94,341.07 3465,325 v1(3560,325)
INA_SDA_s: R35.1 U3.46 U6.4 | length 2007.3
  Top Layer w10: U3.46 2847.94,1725.38 2847.94,1827.94 v1(3250,2230) ; R35.1 3509.54,2462.5 3541.02,2493.98 ; v1(3535,2445) 3541.02,2451.02 3541.02,2493.98 ; U6.4 3591.72,2544.69 3541.02,2493.98
  Bottom Layer w10: v1(3250,2230) 3430,2230 3535,2335 v1(3535,2445)
INA_trigger: R30.1 R38.1 U3.41 | length 894
  Top Layer w10: U3.41 2530,1268.24 2530,1335 2755,1560 v3(2835,1560)
  Bottom Layer w15: v3(2835,1560) 2980,1705 3037.81,1705 3050,1717.19 R38.1 3052.5,1722.5 3052.5,1632.5 R30.1
NetC6_1: C6.1 D2.2 IC1.7 IC1.8 R5.2 | length 2384.5
  Top Layer w25: D2.2 515.91,2805 541.87,2830.96 541.87,2861.87 v2(655,2975) ; R5.2 1255,2070 1370,2185 1370,2420 1390,2440 IC1.7 ; IC1.8 IC1.7 ; v2(1570,2605) 1622.46,2552.54 1622.46,2495.41 1662.87,2455 C6.1 1660,2440 IC1.7
  Bottom Layer w25: v2(655,2975) 1200,2975 v2(1570,2605)
NetC7_2: C7.2 R5.1 U1.1 | length 639.2
  Top Layer w15: v1(990,2225) 995,2225 1014,2206 C7.2 1050,2201 R5.1 ; U1.1 1066.34,2451.34 v1(1110,2495)
  Bottom Layer w15: v1(990,2225) 990,2285 1110,2405 v1(1110,2495)
NetC8_1: C8.1 R6.1 | length 142.1
  Top Layer w25: C8.1 490,2340 R6.1
NetC20_2: C20.2 U2.4 | length 257.5
  Top Layer w15: U2.4 1280.12,1299.88 1295,1285 v3(1345,1285)
  Bottom Layer w15: v3(1345,1285) 1345,1334 1400.94,1389.94 1400.94,1393.88 1417.06,1410 C20.2
NetC21_1: C21.1 R20.2 VR1.3 | length 418.7
  Top Layer w25: C21.1 1122,202 1122,359.44 R20.2 1126.78,368.22 1363.22,368.22 VR1.3
NetC22_1: C22.1 C23.2 | length 152.4
  Top Layer w25: C23.2 977.72,351.5 977.72,200.5 C22.1
NetC27_1: C27.1 R24.2 U5.10 | length 214.6
  Top Layer w10: U5.10 3785.69,474.37 C27.1@3793.22,466.84 ; R24.2 3795,469 C27.1
NetC27_2: C27.2 R26.1 U5.9 | length 387.3
  Top Layer w10: U5.9@3690.16,454.17 3735.83,454.17
  Top Layer w15: U5.9 U5.9@3690.16,454.17 ; 3735.83,454.17 3760,430 3760,400.06 3810.06,350 C27.2 3814,196.82 3785,167.81 R26.1
NetC35_1: C35.1 R32.2 U6.10 | length 328.5
  Top Layer w10: C35.1 3702.81,2820 3775,2747.81 R32.2 3775,2732.19 3834.29,2672.89 U6.10
NetC35_2: C35.2 R37.1 U6.9 | length 353.9
  Top Layer w10: R37.1 3621.06,2740 3641.06,2720 C35.2 3648.94,2720 3784.88,2584.06 U6.9
NetC38_1: C38.1 C41.1 | length 126.9
  Top Layer w15: C41.1 2764.94,805 2830.88,739.06 2833.88,739.06 2850,722.94 C38.1
NetD3_2: D3.2 L2.1 U4.4 | length 719.8
  Top Layer w25: D3.2 498.58,1121.42 548.07,1071.93 U4.4 863.44,1071.93 954.37,981 L2.1
NetD4_1: D4.1 K1.COIL2 Q1.3 | length 955.4
  Bottom Layer w15: Q1.3 3280.16,425.39 D4.1 3799.13,730.24 3835.59,693.78 K1.COIL2
NetD5_1: D5.1 K2.COIL2 Q2.3 | length 814
  Bottom Layer w15: Q2.3 3345,1567.28 3349.31,1571.59 3506.59,1571.59 3610,1675 3610,1766.89 3585,1791.89 D5.1 3694.99,1880.24 3720.23,1855 K2.COIL2
NetIC1_2: IC1.2 U1.15 | length 215.2
  Top Layer w10: U1.15 1056.46,2394.96 1084.71,2394.96 1099.75,2410 1191.38,2410 1221.38,2440 IC1.2
NetIC1_4: IC1.4 U1.13 | length 208.5
  Top Layer w10: U1.13 1068.15,2355.47 1068.27,2355.35 1068.27,2345.86 1074.13,2340 IC1.4
NetJ1_2: J1.2 R23.1 | length 238.9
  Top Layer w10: R23.1 4231.23,1470 4245.12,1483.9 J1.2
NetJ1_3: J1.3 R22.1 | length 256.1
  Top Layer w10: R22.1 4210.42,1565 4265.93,1509.49 J1.3
NetK1_COM: K1.COM P3.1 | length 905.4
  Bottom Layer w15: K1.COM 4290,410.04 P3.1
NetK1_NO: K1.NO R25.2 R26.2 | length 1574.6
  Top Layer w15: R25.2 3912.19,430 3875,392.81 R26.2 3875,152.19 3889.68,137.5 3897.5,137.5 3985,50 4400,50 4440,90 4440,430 4329.09,540.91 K1.NO
NetK2_COM: K2.COM P5.1 | length 1121.3
  Top Layer w25: K2.COM 3971.22,2091.22 4375,2495 P5.1
NetK2_NO: K2.NO R36.2 R37.2 | length 1751.7
  Top Layer w10: R37.2 3455,2867.19 R36.2@3570,2982.19 ; v1(3570,2895) R36.2@3570,2982.19 ; R36.2 3570,2990 R36.2@3570,2982.19
  Bottom Layer w10: v1(3570,2895) 3570,2875 4038.61,2406.39 4038.61,2141.39 K2.NO
NetLED1_1: LED1.1 R10.2 | length 100
  Top Layer w25: LED1.1 R10.2
NetLED1_2: LED1.2 U1.5 | length 433.6
  Top Layer w10: v1(695,2650) LED1.2 ; v1(895,2490) 923.66,2461.34 U1.5
  Bottom Layer w10: v1(695,2650) 855,2490 v1(895,2490)
NetLED2_1: LED2.1 R11.2 | length 123.8
  Top Layer w15: LED2.1@1048.5,2821.5 LED2.1
  Top Layer w25: R11.2 LED2.1@1048.5,2821.5
NetLED2_2: LED2.2 U1.3 | length 316.4
  Top Layer w10: U1.3 980.16,2511.1 995,2525.94 v1(995,2530) ; v1(995,2640) 1016.43,2661.43 1031.43,2661.43 1050,2680 LED2.2
  Bottom Layer w10: v1(995,2530) v1(995,2640)
NetLED3_2: LED3.2 R15.2 | length 299.1
  Top Layer w15: LED3.2 1760.75,855.75 v3(1815,910)
  Bottom Layer w15: v3(1815,910) 1856.21,910 1905,861.21 1905,814 R15.2
NetLED4_2: LED4.2 R18.2 | length 123.6
  Top Layer w10: LED4.2 1625,920 R18.2
NetLED5_1: LED5.1 R19.1 | length 160.6
  Top Layer w25: R19.1 LED5.1
NetP2_3: P2.3 R16.1 | length 559.8
  Bottom Layer w15: P2.3 1862.81,1750 2085,1527.81 R16.1
NetP2_4: P2.4 R17.2 | length 200.6
  Bottom Layer w15: R17.2 1485,1710 P2.4
NetP3_2: P3.2 R24.1 R25.1 | length 467.5
  Top Layer w15: R24.1 3885,542.19 3970,457.19 3970,382.18 3927.81,340 3984.14,283.67 3984.14,281.64 4025.79,240 P3.2
NetP5_2: P5.2 R32.1 R36.1 | length 692.2
  Top Layer w25: R36.1 3670,2992.19 3865,2797.19 R32.1 4075,2740 P5.2
NetQ1_1: Q1.1 R30.2 R31.2 | length 2166.3
  Bottom Layer w10: R31.2 3124,61 3155,30 3259.09,30 3317.56,88.46 Q1.1
  Bottom Layer w15: R31.2 3116.19,100 2985,231.19 2985,575 3410,1000 3410,1357.18 3145,1622.19 R30.2
NetQ2_1: Q2.1 R38.2 R39.2 | length 398.5
  Bottom Layer w15: R39.2 3170,1755 3160,1745 3152.19,1745 3140,1732.81 R38.2 3187.45,1725 3268.02,1644.43 3303.29,1644.43 3307.6,1640.12 Q2.1
NetR7_1: R7.1 R8.2 U1.2 | length 595.6
  Top Layer w10: U1.2 999.84,2479.84 1027.18,2507.18 1047.18,2507.18 v1(1048.59,2508.59)
  Top Layer w25: R7.1 760,2568.02 R8.2 767.81,2430 812.81,2385 v3(840,2385)
  Bottom Layer w10: v3(840,2385) 840,2390 945,2495 1015,2495 1026.24,2506.24 1046.24,2506.24 v1(1048.59,2508.59)
NetR27_1: R27.1 U5.3 | length 213.6
  Top Layer w10: R27.1 3320,450 3429.71,450 3444.72,435 U5.3
NetR33_1: R33.1 U6.3 | length 222.3
  Top Layer w10: R33.1 3548.44,2560 3553.44,2565 3637.8,2565 3637.92,2564.88 3664.49,2564.88 U6.3
NetU4_2: U4.2 VR1.2 | length 1388.1
  Top Layer w25: U4.2 695.35,926.95 773.05,926.95 815,885 815,720 925,610 1425,610 1485,550 1485,377.5 1382.5,275 VR1.2
OSCIN: C38.2 R40.2 U3.5 Y2.2 | length 1268.5
  Top Layer w10: U3.5 2262.99,1278.86 2297.21,1244.64 2300.36,1244.64 v1(2320,1225)
  Top Layer w25: v4(2740,1085) 2783.23,1041.77 Y2.2 2870.03,968.94 2888.12,950.85 2976.34,950.85 3012.19,915 R40.2 3027.81,915 3040,902.81 3040,895 3080,855 3080,790 3009,719 C38.2
  Bottom Layer w10: v1(2320,1225) 2385,1160 2592.97,1160 2672.97,1080 2735,1080 v4(2740,1085)
OSCOUT: C41.2 R40.1 U3.6 Y2.1 | length 1613.3
  Top Layer w10: U3.6 2297.5,1216.42 2297.5,1208.71 2321.21,1185 2335,1185 2382.13,1232.13 2382.13,1240.06 v1(2385,1242.93)
  Top Layer w25: v4(2670,1420) 2746.46,1420 2778.23,1388.23 ; Y2.1 2778.23,1388.23 ; R40.1 2844.94,825 2764.94,905 C41.2 2757.06,905 2740.94,921.12 2740.94,925.06 2695,971 2695,1305 2778.23,1388.23
  Bottom Layer w10: v1(2385,1242.93) 2562.07,1420 v4(2670,1420)
PA3: C14.2 U3.13 | length 1123.2
  Top Layer w10: C14.2 v1@2015,518.74 ; v1(1955,665) 1955,888.11 U3.13
  Top Layer w25: v1@2015,518.74 v1(2015,520)
  Bottom Layer w10: v1(1955,665) 1983.93,636.07 2015,605 v1(2015,520)
PA4: C14.7 U3.14 | length 1301.7
  Top Layer w10: C14.7 1555,290 1555,460 1600,505 1705,505 1830,630 1965,630 2070,735 2070,975 2179.38,1084.38 U3.14
PA5: C14.6 U3.15 | length 1193.1
  Top Layer w10: C14.6 1575,348.74 1575,445 1610,480 1715,480 1840,605 1966.21,605 2100,738.79 2100,977.44 U3.15
PA6: C14.5 U3.16 | length 997.4
  Top Layer w10: C14.5 1845.04,585 1970,585 2120,735 2120,969.6 U3.16
PA7: C14.3 U3.17 | length 962.1
  Top Layer w10: C14.3 2140,722.48 2140,961.76 U3.17
PA11: R23.2 U3.32 | length 2302.1
  Top Layer w10: U3.32 2549.46,992.3 2549.46,750.54 2770,530 v1(3035,530) ; v1(3930,1455) 3934.06,1455 3949.06,1470 R23.2
  Bottom Layer w10: v1(3035,530) 3541.5,1036.5 3541.5,1047.41 3547.36,1053.26 3547.36,1072.36 v1(3930,1455)
PA12: R21.2 R22.2 U3.33 | length 2619.7
  Top Layer w10: U3.33 2585,984.6 2585,750 2760,575 v1(3045,575) ; v1(3555,1160) 3765,1370 3920,1370 ; R21.2 3920,1370 ; R22.2 4040,1557.19 4025.32,1542.5 3882.5,1542.5 3855,1515 3855,1435 3920,1370
  Bottom Layer w10: v1(3045,575) 3047.87,577.87 3047.87,587.87 3505,1045 3505,1110 v1(3555,1160)
PC13: R18.1 U3.2 | length 900.3
  Top Layer w10: R18.1 1850,1015 v1(2075,1240) ; v1(2270,1405) 2270,1401.64 2280,1391.64 2280,1346.56 2304.66,1321.9 U3.2
  Bottom Layer w10: v1(2075,1240) 2240,1405 v1(2270,1405)
PC14: C39.2 U3.3 Y1.4 | length 2292.1
  Top Layer w10: v1(2120,1410) 2186.22,1410 2289.52,1306.7 U3.3 ; v1(3125,890) 3130,895 C39.2
  Top Layer w15: Y1.4 3072.01,1022.93 3130,964.94 C39.2
  Bottom Layer w10: v1(2120,1410) 2117.07,1410 2099.09,1392.02 2097.02,1392.02 1915,1210 1915,1045 2165,795 3030,795 v1(3125,890)
PC15: C42.2 U3.4 Y1.1 | length 2292.3
  Top Layer w10: v1(2166.43,1378.57) 2169.3,1375.7 2194.31,1375.7 2276.82,1293.18 U3.4 ; v1(3195,1040) 3197.99,1042.99 Y1.1 ; C42.2@3335.06,1185 C42.2
  Top Layer w15: Y1.1 3286.8,1136.73 C42.2@3335.06,1185
  Bottom Layer w10: v1(2166.43,1378.57) 2123.57,1378.57 1940,1195 1940,1060 2185,815 2970,815 v1(3195,1040)
PH: C3.2 IC1.5 IC1.6 L1.1 U1.14 | length 1334.6
  Top Layer w10: U1.14 1122.5,2375.16 1122.66,2375 v1(1175,2375)
  Top Layer w15: IC1.6 IC1.5 1520,2340 1540,2360 v3(1540,2390)
  Top Layer w25: v2(1470,2575) 1470,2689.94 1488.62,2708.56 1557.57,2708.56 1654.37,2805.35 L1.1
  Bottom Layer w15: v1(1175,2375) 1350,2550 1450,2550 v2@1470,2570 ; v2(1470,2575) v2@1470,2570 ; v3(1540,2390) 1540,2478.67 1475.12,2543.55 1475.12,2564.88 v2@1470,2570
REGN: C2.2 D1.1 U1.12 | length 885.2
  Top Layer w10: U1.12 1019.53,2308.13 1019.65,2308.01 1106.55,2308.01 1114.56,2300 v3(1121.32,2300)
  Top Layer w15: v3(1120,2800) 1175,2855 D1.1
  Bottom Layer w15: v3(1120,2800) 1116.17,2796.17 1116.17,2782.39 1115,2781.21 1115,2652.12 1165,2602.12 ; v3(1121.32,2300) 1121.32,2376.32 1165,2420 1165,2602.12 ; C2.2 1165,2684 1165,2602.12
RESET: C15.2 R14.2 SW1.2 U3.7 | length 761.1
  Top Layer w10: R14.2 2010,1505 v1(2035,1480) ; v1(2060,1405) 2061.95,1403.05 2081.95,1403.05 2185,1300 2186.08,1300 U3.7
  Top Layer w15: R14.2 1975,1632.94 2015,1672.94 SW1.2
  Bottom Layer w10: v1(2035,1480) 2035,1430 v1(2060,1405)
SRN: C1.2 C4.1 C9.1 C11.1 J3.1 R1.1 R9.1 U1.9 | length 6735.9
  Top Layer w15: 920,2271.14 960.47,2311.61 U1.9
  Top Layer w25: C11.1 422.94,1920 517.94,2015 532.81,2015 545,2027.19 R9.1 v2(420,2035) ; 920,2271.14 920,2210 890,2180 C9.1 902.13,2050 942.54,2009.59 942.54,1962.46 v2(1090,1815) ; R1.1 C1.2 2614,2920 C4.1 2615.06,2915 2596.44,2896.38 2596.44,2892.44 2545,2841 2545,2763.36 2495,2713.36 v2(2495,2670)
  Bottom Layer w25: v2(420,2035) 190,1805 190,1110 630,670 730,670 ; J3.1 630,570 730,670 ; v2(2495,2670) 2495,2315 2220,2040 1315,2040 v2(1090,1815) 1060,1785 1060,1000 730,670
SRP: C1.1 L1.2 R1.2 U1.10 | length 2138.4
  Top Layer w10: 955,2270 980.04,2295.04 980.04,2318.54 U1.10
  Top Layer w15: v2(955,2160) 955,2270
  Top Layer w25: v2(1800,2592.82) 1800,2595 1915.65,2710.65 1964.07,2710.65 2055,2801.57 L1.2 2125,2830 R1.2 2466,2830 C1.1
  Bottom Layer w25: v2(955,2160) 1025,2160 1030,2155 1440,2155 1800,2515 v2(1800,2592.82)
SWDCLK: C30.2 U3.37 | length 2133.4
  Top Layer w10: U3.37 2555.48,1181.42 2659.06,1285 v1(2660,1285)
  Bottom Layer w10: v1(2660,1285) 2752.5,1377.5 2752.5,1577.5 3155,1980 C30.2
SWDIO: C30.3 U3.34 | length 2409.4
  Top Layer w10: U3.34 2527.98,1070.74 2593.72,1005 2650,1005 2665,1020 2665,1146.64 2655,1156.64 v1(2655,1160)
  Bottom Layer w10: v1(2655,1160) 2627.5,1187.5 2627.5,1307.5 2710,1390 2710,1585 3055,1930 C30.3
TS: R2.1 R3.2 U1.4 | length 221.2
  Top Layer w10: 948.55,2475.07 960.47,2463.15 U1.4
  Top Layer w15: 948.55,2475.07 R3.2 R2.1
VBAT: C28.2 C29.1 J2.1 J3.2 U4.1 | length 1138.2
  Top Layer w25: J2.1 240,202.5 385,347.5 C29.1 ; J3.2 455.28,470 430.28,495 C29.1 ; U4.1 638.95,871.14 466.81,699 C28.2 365,605.67 385,585.67 C29.1
VCC3V3: C14.1 C16.2 C17.2 C25.1 C26.1 C30.4 C31.2 C32.1 C33.1 C34.2 C36.2 C37.2 C40.2 LED3.1 LED4.1 P2.1 P2.2 R14.1 R27.2 R28.2 R29.2 R33.2 R34.2 R35.2 U2.5 U3.9 U3.24 U3.36 U3.48 U5.1 U5.2 U5.6 U5.8 U6.1 U6.2 U6.6 U6.8 | length 11893.8
  Top Layer w10: R14.1@1885,1497.19 1899.68,1482.5 1907.5,1482.5 ; 2150.4,1280 U3.9 2360,1070.4 ; U3.24 2360,986.89 2360,1070.4 ; U3.48 2455,1388.11 2455,1425 2435,1445 2430,1440 ; U3.36 2523.11,1130 2489.19,1130 2429.6,1070.4 2360,1070.4
  Top Layer w15: C17.2 C17.2@916,1415 ; U2.5@1277.13,1402.4 U2.5@1290.94,1402.4 ; P2.2@1525,1636.46 P2.2 ; LED4.1@1622.5,713.5 LED4.1 ; C14.1 1727.48,152.48 1747.48,152.48 ; R14.1@1885,1497.19 R14.1 R14.1@1885,1512.81 ; 1945,1445 2435,1445 2338.94,1541.06 C36.2 ; 2305,695 2305,922.32 2301.34,925.97 2301.34,928.23 U3.24 ; C25.1 C25.1@3076,345 ; C26.1@3211,345 C26.1 ; R27.2@3310,350 R27.2 ; R27.2@3322.81,355 3335,342.82 3335,335.72 3336.69,334.03 ; R33.2 3355,2567.81 3367.19,2580 3375,2580 3435,2640 3609.29,2640 3645.55,2603.74 U6.1 U6.2 3740.64,2584.06 3760.32,2564.37 ; R28.2@3390,255 3400,245 R28.2@3400,243.83 ; R28.2 3412.19,237.81 R28.2@3412.19,223.83 ; U5.1 U5.2 3574.64,454.68 3633.69,395.63 U5.6 ; R29.2@3672.81,221.17 3672.81,232.81 3689.65,249.65 U5.6 ; U5.8 3721.28,435 3735.41,420.87 3735.41,404.42 3726.63,395.63 U5.6 ; U6.8 3760.32,2564.37 ; C32.1 C33.1 3878.74,2500 3853.74,2525 U6.6 3832.62,2526.67 3798.02,2526.67 3760.32,2564.37
  Top Layer w25: C17.2@916,1415 C16.2@1029.94,1415 ; C16.2 1026,1476 1096.29,1546.29 1133.24,1546.29 1270.96,1408.57 U2.5@1270.96,1404.07 ; U2.5@1290.94,1402.4 P2.2@1525,1636.46 ; P2.2 P2.1 1747.81,1650 R14.1@1885,1512.81 ; LED4.1@1622.5,713.5 1545,791 1545,1045 1885,1385 R14.1@1885,1497.19 ; LED4.1 LED3.1 ; C14.1 2856,135 C25.1 ; 1747.48,152.48 1762.48,152.48 2305,695 ; 1907.5,1482.5 1945,1445 2110,1280 2150.4,1280 ; C36.2 C34.2 C40.2 C37.2 2338.94,1911.5 2437.44,2010 2800,2010 2955,2165 2955,2772.81 ; C31.2 2754.94,2915 2897.67,3057.73 2947.73,3057.73 C30.4 2955,2772.81 ; C25.1@3076,345 C26.1@3211,345 ; C26.1 R27.2@3310,350 ; 3336.69,334.03 3336.69,308.31 3380,265 3392.82,265 R28.2@3392.82,255 ; R34.2 R34.2@3355,2372.81 ; R33.2 R35.2 R34.2@3355,2372.81 ; R28.2@3412.19,223.83 3471.01,165 3616.64,165 R29.2@3672.81,221.17 ; 2955,2772.81 R34.2@3355,2372.81
VFB: C5.2 R4.1 R9.2 U1.8 | length 740.2
  Top Layer w10: 885,2240 885,2316.81 912.41,2344.22 912.41,2355.35 912.52,2355.47 U1.8
  Top Layer w15: R9.2@635,2027.19 635,2037.81 R9.2@647.19,2050 ; C5.2@669.56,1926.44 C5.2
  Top Layer w25: R4.1 C5.2@669.56,1926.44 ; R9.2@635,2027.19 676,1986.19 C5.2 ; R9.2@647.19,2050 695,2050 885,2240
VREF: C10.1 R3.1 R10.1 R11.1 U1.6 U1.7 | length 773.3
  Top Layer w10: U1.7 U1.6
  Top Layer w15: C10.1 798.62,2243.62 798.62,2265.87 880.41,2347.66 880.41,2376.46 898.94,2395 ; R10.1 802.81,2730 858.55,2674.26 R3.1 858.55,2431.45 895,2395 898.94,2395 ; U1.6 899.1,2394.84 898.94,2395 ; R11.1@925.33,2730 R11.1
  Top Layer w25: R10.1@802.81,2730 R11.1@925.33,2730
VSOLAR: D2.1 P1.2 R6.2 R7.2 | length 774.3
  Top Layer w25: D2.1 303.78,2805 220,2721.22 P1.2 457.19,2540 482.19,2565 R6.2 497.19,2572.18 518.81,2572.18 519.64,2573.02 R7.2
pads on no net: C14.4 IC1.1 J1.4 K1.NC K2.NC U3.1 U3.10 U3.11 U3.12 U3.18 U3.19 U3.21 U3.22 U3.25 U3.26 U3.27 U3.28 U3.29 U3.30 U3.31 U3.38 U3.39 U3.40

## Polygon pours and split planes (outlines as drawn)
GND on Top Layer "top poly" (solid, remove dead copper, pour order 0): 0,3225 5,3220 4555,3220 4555,-25 4545,-15 -10,-15 -10,3230
GND on Bottom Layer "bottom poly" (solid, remove dead copper, pour order 1): -5,3215 5,3225 4545,3225 4545,5 4550,0 0,0 0,3205 -15,3220

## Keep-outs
Keep-Out Layer:
  lines w10: 0,3225 0,-10 4550,-10 4550,3220 10,3220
